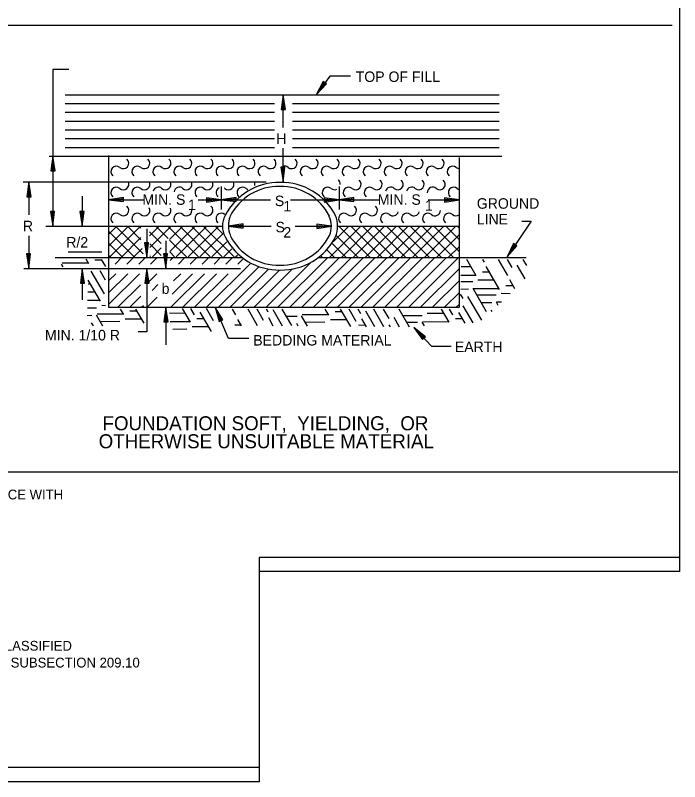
# Model space of a CAD drawing. Extents: x 0 to 390, y 0 to 265.
# Drawn here: x 271.5 to 390, y 0 to 136.7 of the extents above; entities that cross this region are included whole.
import ezdxf

# ---------------------------------------------------------------- set-up
doc = ezdxf.new("R2010")
doc.units = 0
doc.layers.add('D_Details', color=7, linetype='Continuous')
doc.layers.add('Default', color=7, linetype='Continuous')

msp = doc.modelspace()

# ---------------------------------------------------------------- linework, layer by layer
at = {"layer": 'D_Details'}
for p, q in [((-0.22, 135.01), (388.66, 135.01)), ((281.04, 127.06), (278.19, 127.06)), ((278.19, 127.06), (278.19, 111.61)), ((327.59, 125.86), (325.18, 122.57)), ((331.32, 125.86), (327.59, 125.86)), ((326.4, 124.93), (325.18, 122.57)), ((325.18, 122.57), (327.01, 124.49)), ((325.57, 123.1), (326.55, 124.82)), ((326.86, 124.6), (325.57, 123.1)), ((326.17, 123.94), (326.63, 124.76)), ((326.78, 124.65), (326.17, 123.94)), ((327.01, 124.49), (326.4, 124.93)), ((280.39, 122.57), (357.83, 122.57)), ((319.27, 122.57), (318.93, 119.95)), ((319.12, 119.95), (319.27, 121.91)), ((319.68, 119.95), (319.27, 122.57)), ((319.27, 116.71), (319.27, 122.57)), ((319.27, 121.91), (319.49, 119.95)), ((280.39, 121), (317.76, 121)), ((319.21, 119.95), (319.29, 120.88)), ((319.29, 120.88), (319.4, 119.95)), ((320.94, 121), (357.83, 121)), ((280.39, 119.44), (317.76, 119.44)), ((318.93, 119.95), (319.68, 119.95)), ((320.94, 119.44), (357.83, 119.44)), ((280.39, 117.87), (317.76, 117.87)), ((320.94, 117.87), (357.83, 117.87)), ((280.39, 116.31), (317.76, 116.31)), ((320.94, 116.31), (357.83, 116.31)), ((280.39, 114.74), (317.76, 114.74)), ((320.94, 114.74), (357.83, 114.74)), ((280.39, 113.17), (317.76, 113.17)), ((319.27, 107), (319.27, 113.06)), ((320.94, 113.17), (357.83, 113.17)), ((277.54, 111.61), (358.26, 111.61)), ((278.2, 111.61), (277.86, 108.98)), ((278.05, 108.98), (278.2, 110.95)), ((278.19, 111.61), (278.19, 107)), ((278.61, 108.98), (278.2, 111.61)), ((278.2, 110.95), (278.42, 108.98)), ((288.16, 111.72), (288.16, 84.64)), ((350.71, 84.64), (350.71, 111.39)), ((278.14, 108.98), (278.21, 109.92)), ((278.21, 109.92), (278.33, 108.98)), ((319.61, 109.63), (318.86, 109.63)), ((318.86, 109.63), (319.27, 107)), ((319.27, 107.66), (319.04, 109.63)), ((319.25, 108.69), (319.14, 109.63)), ((319.33, 109.63), (319.25, 108.69)), ((319.27, 107), (319.61, 109.63)), ((319.42, 109.63), (319.27, 107.66)), ((277.86, 108.98), (278.61, 108.98)), ((272.94, 107), (316.27, 107)), ((273.92, 107), (273.59, 104.38)), ((274.34, 104.38), (273.92, 107)), ((273.92, 107), (273.92, 101.17)), ((278.19, 107), (278.19, 99.11)), ((273.77, 104.38), (273.92, 106.35)), ((273.87, 104.38), (273.94, 105.32)), ((273.92, 106.35), (274.15, 104.38)), ((273.94, 105.32), (274.05, 104.38)), ((308.25, 106.2), (308.25, 102.07)), ((329.25, 106.2), (329.25, 102.07)), ((273.59, 104.38), (274.34, 104.38)), ((283.45, 104.48), (283.45, 99.11)), ((290.79, 104.24), (288.16, 103.83)), ((288.82, 103.83), (290.79, 104.05)), ((289.85, 103.84), (290.79, 103.96)), ((290.79, 103.49), (290.79, 104.24)), ((308.25, 103.83), (305.63, 104.16)), ((305.63, 104.16), (305.63, 103.41)), ((305.63, 103.98), (307.6, 103.83)), ((310.88, 104.24), (308.25, 103.83)), ((308.91, 103.83), (310.88, 104.05)), ((309.94, 103.84), (310.88, 103.96)), ((310.88, 103.49), (310.88, 104.24)), ((329.25, 103.83), (326.62, 104.16)), ((326.62, 104.16), (326.62, 103.41)), ((326.62, 103.98), (328.59, 103.83)), ((331.87, 104.24), (329.25, 103.83)), ((329.9, 103.83), (331.87, 104.05)), ((330.93, 103.84), (331.87, 103.96)), ((331.87, 103.49), (331.87, 104.24)), ((350.71, 103.83), (348.08, 104.16)), ((348.08, 104.16), (348.08, 103.41)), ((348.08, 103.98), (350.05, 103.83)), ((288.16, 103.83), (290.79, 103.49)), ((288.16, 103.83), (294.47, 103.83)), ((290.79, 103.68), (288.82, 103.83)), ((290.79, 103.77), (289.85, 103.84)), ((304.13, 103.83), (308.25, 103.83)), ((305.63, 103.88), (306.57, 103.81)), ((305.63, 103.41), (308.25, 103.83)), ((307.6, 103.83), (305.63, 103.6)), ((306.57, 103.81), (305.63, 103.69)), ((308.13, 103.83), (309.55, 103.83)), ((308.25, 103.83), (310.88, 103.49)), ((308.25, 103.83), (317.06, 103.83)), ((310.88, 103.68), (308.91, 103.83)), ((310.88, 103.77), (309.94, 103.84)), ((320.58, 103.83), (329.25, 103.83)), ((326.62, 103.88), (327.56, 103.81)), ((326.62, 103.41), (329.25, 103.83)), ((328.59, 103.83), (326.62, 103.6)), ((327.56, 103.81), (326.62, 103.69)), ((328.07, 103.83), (329.6, 103.83)), ((329.25, 103.83), (331.87, 103.49)), ((329.25, 103.83), (336.46, 103.83)), ((331.87, 103.68), (329.9, 103.83)), ((331.87, 103.77), (330.93, 103.84)), ((345.17, 103.83), (350.71, 103.83)), ((348.08, 103.88), (349.02, 103.81)), ((348.08, 103.41), (350.71, 103.83)), ((350.05, 103.83), (348.08, 103.6)), ((349.02, 103.81), (348.08, 103.69)), ((278.53, 101.74), (277.78, 101.74)), ((277.78, 101.74), (278.2, 99.11)), ((278.2, 99.77), (277.97, 101.74)), ((278.18, 100.8), (278.06, 101.74)), ((278.25, 101.74), (278.18, 100.8)), ((278.2, 99.11), (278.53, 101.74)), ((278.35, 101.74), (278.2, 99.77)), ((283.79, 101.74), (283.04, 101.74)), ((283.04, 101.74), (283.45, 99.11)), ((283.45, 99.77), (283.23, 101.74)), ((283.43, 100.8), (283.32, 101.74)), ((283.51, 101.74), (283.43, 100.8)), ((283.45, 99.11), (283.79, 101.74)), ((283.6, 101.74), (283.45, 99.77)), ((363.52, 99.99), (359.25, 93.63)), ((361.88, 99.99), (363.52, 99.99)), ((276.99, 99.11), (283.13, 99.11)), ((283.13, 99.11), (308.47, 99.11)), ((288.22, 97.72), (289.49, 99)), ((288.22, 95.6), (291.59, 98.97)), ((288.34, 93.6), (293.69, 98.95)), ((294.31, 94.17), (289.48, 99)), ((293.93, 96.67), (291.63, 98.97)), ((293.93, 98.79), (293.77, 98.95)), ((294.95, 98.67), (294.95, 93.52)), ((295.48, 97.4), (297.12, 99.04)), ((295.49, 95.29), (299.24, 99.04)), ((298.77, 96.92), (296.65, 99.04)), ((304.18, 93.63), (298.78, 99.04)), ((299.04, 96.72), (301.35, 99.03)), ((299.06, 94.62), (303.47, 99.02)), ((300.2, 93.63), (305.58, 99.02)), ((306.3, 93.63), (300.9, 99.03)), ((302.32, 93.63), (307.7, 99.01)), ((308.42, 93.63), (303.03, 99.03)), ((310.54, 93.63), (305.15, 99.02)), ((308.53, 97.77), (307.28, 99.02)), ((312.16, 99.52), (309.54, 99.11)), ((309.54, 99.11), (312.16, 98.77)), ((309.54, 99.11), (317.17, 99.11)), ((310.19, 99.11), (312.16, 99.34)), ((312.16, 98.96), (310.19, 99.11)), ((311.22, 99.13), (312.16, 99.24)), ((312.16, 99.06), (311.22, 99.13)), ((312.16, 98.77), (312.16, 99.52)), ((321.41, 99.11), (327.89, 99.11)), ((327.89, 99.11), (325.27, 99.45)), ((325.27, 99.45), (325.27, 98.7)), ((325.27, 99.26), (327.23, 99.11)), ((325.27, 99.17), (326.2, 99.09)), ((325.27, 98.7), (327.89, 99.11)), ((327.23, 99.11), (325.27, 98.89)), ((326.2, 99.09), (325.27, 98.98)), ((327.61, 93.59), (333.07, 99.04)), ((328.22, 96.32), (330.95, 99.04)), ((329, 99.11), (350.71, 99.11)), ((334.73, 93.58), (329.27, 99.04)), ((329.73, 93.59), (335.19, 99.04)), ((336.86, 93.58), (331.39, 99.04)), ((331.85, 93.58), (337.31, 99.04)), ((338.98, 93.57), (333.51, 99.04)), ((333.97, 93.58), (339.43, 99.04)), ((341.1, 93.57), (335.63, 99.04)), ((336.09, 93.58), (341.55, 99.04)), ((343.23, 93.57), (337.76, 99.04)), ((338.2, 93.58), (343.67, 99.04)), ((345.35, 93.57), (339.88, 99.04)), ((340.32, 93.57), (345.79, 99.04)), ((347.47, 93.56), (342, 99.04)), ((342.44, 93.57), (347.91, 99.04)), ((349.6, 93.56), (344.12, 99.04)), ((344.56, 93.57), (350.03, 99.04)), ((350.64, 94.64), (346.24, 99.04)), ((350.66, 96.74), (348.36, 99.04)), ((350.69, 98.84), (350.48, 99.04)), ((273.92, 97.41), (273.92, 91.55)), ((292.76, 93.6), (288.22, 98.14)), ((297.56, 96.01), (295.47, 98.1)), ((304.44, 93.63), (308.53, 97.73)), ((332.61, 93.58), (328.79, 97.4)), ((346.68, 93.57), (350.67, 97.56)), ((290.64, 93.6), (288.22, 96.02)), ((290.46, 93.6), (293.93, 97.07)), ((295.29, 96.15), (294.54, 96.15)), ((294.54, 96.15), (294.95, 93.52)), ((294.95, 94.18), (294.73, 96.15)), ((294.93, 95.21), (294.82, 96.15)), ((295.01, 96.15), (294.93, 95.21)), ((294.95, 93.52), (295.29, 96.15)), ((295.1, 96.15), (294.95, 94.18)), ((297.53, 93.91), (295.49, 95.96)), ((298.35, 96.48), (298.35, 91.55)), ((302.06, 93.63), (299.04, 96.65)), ((306.56, 93.63), (309.26, 96.34)), ((330.49, 93.59), (328.04, 96.03)), ((360.37, 96.04), (359.25, 93.63)), ((359.62, 94.18), (360.53, 95.94)), ((360.84, 95.73), (359.62, 94.18)), ((360.17, 95.04), (360.6, 95.88)), ((360.76, 95.78), (360.17, 95.04)), ((360.99, 95.62), (360.37, 96.04)), ((280.93, 94.51), (286.96, 94.51)), ((292.58, 93.6), (294.13, 95.15)), ((296, 93.67), (297.55, 95.23)), ((299.94, 93.63), (299.06, 94.51)), ((308.68, 93.63), (310.14, 95.1)), ((328.36, 93.59), (327.14, 94.81)), ((348.8, 93.56), (350.65, 95.41)), ((359.25, 93.63), (360.99, 95.62)), ((274.26, 94.17), (273.51, 94.17)), ((273.51, 94.17), (273.92, 91.55)), ((273.92, 92.2), (273.7, 94.17)), ((273.9, 93.24), (273.79, 94.17)), ((273.98, 94.17), (273.9, 93.24)), ((273.92, 91.55), (274.26, 94.17)), ((274.07, 94.17), (273.92, 92.2)), ((278.63, 93.52), (311.99, 93.52)), ((284.62, 92.42), (284.14, 93.24)), ((287.02, 93.03), (285.73, 93.04)), ((287.65, 91.95), (286.92, 93.2)), ((288.16, 93.34), (288.34, 93.52)), ((288.52, 93.6), (288.22, 93.9)), ((289.3, 92.35), (290.47, 93.52)), ((291.42, 92.35), (292.59, 93.52)), ((293.54, 92.35), (294.71, 93.52)), ((295.64, 93.69), (295.5, 93.83)), ((295.66, 92.35), (296.83, 93.52)), ((298.69, 94.17), (297.94, 94.17)), ((297.94, 94.17), (298.35, 91.55)), ((298.35, 92.2), (298.12, 94.17)), ((298.33, 93.24), (298.22, 94.17)), ((298.41, 94.17), (298.33, 93.24)), ((298.35, 91.55), (298.69, 94.17)), ((298.5, 94.17), (298.35, 92.2)), ((299.15, 93.02), (299.66, 93.52)), ((300.61, 92.35), (301.78, 93.52)), ((302.73, 92.35), (303.9, 93.52)), ((304.85, 92.35), (306.02, 93.52)), ((306.97, 92.35), (308.14, 93.52)), ((309.09, 92.35), (310.26, 93.52)), ((310.8, 93.63), (311.13, 93.96)), ((311.21, 92.35), (312.22, 93.36)), ((318.35, 84.64), (327.23, 93.52)), ((320.47, 84.64), (329.35, 93.52)), ((322.59, 84.64), (331.47, 93.52)), ((324.71, 84.64), (333.59, 93.52)), ((325.56, 93.52), (362.64, 93.52)), ((326.24, 93.59), (326.04, 93.79)), ((326.83, 84.64), (335.71, 93.52)), ((328.95, 84.64), (337.83, 93.52)), ((331.07, 84.64), (339.95, 93.52)), ((333.19, 84.64), (342.07, 93.52)), ((335.31, 84.64), (344.19, 93.52)), ((337.43, 84.64), (346.31, 93.52)), ((339.55, 84.64), (348.43, 93.52)), ((341.68, 84.64), (350.55, 93.52)), ((353.71, 90.25), (352.02, 93.19)), ((355.18, 92.71), (354.9, 93.19)), ((359.34, 90.3), (357.68, 93.19)), ((360.13, 91.75), (359.32, 93.19)), ((362.72, 92.11), (362.11, 93.19)), ((280.04, 91.84), (279.76, 92.33)), ((284.54, 92.51), (279.87, 92.52)), ((305.62, 84.64), (313.52, 92.54)), ((307.74, 84.64), (315.01, 91.91)), ((316.23, 84.64), (324.27, 92.69)), ((352.7, 91.87), (351.01, 91.88)), ((357.88, 87.84), (355.52, 91.93)), ((362.46, 89.72), (361.05, 92.18)), ((273.05, 91.55), (311.71, 91.55)), ((283.45, 91.55), (283.12, 88.92)), ((283.3, 88.92), (283.45, 90.89)), ((283.45, 91.55), (283.45, 85.96)), ((283.87, 88.92), (283.45, 91.55)), ((283.45, 90.89), (283.68, 88.92)), ((287.41, 87.07), (285.07, 91.11)), ((287.62, 89.49), (286.64, 91.17)), ((288.16, 91.48), (288.23, 91.55)), ((288.16, 89.36), (289.45, 90.64)), ((288.16, 87.24), (291.57, 90.64)), ((288.16, 85.12), (293.69, 90.64)), ((294.95, 91.55), (294.62, 88.92)), ((294.8, 88.92), (294.95, 90.89)), ((294.95, 91.55), (294.95, 80.26)), ((295.37, 88.92), (294.95, 91.55)), ((294.95, 90.89), (295.18, 88.92)), ((295.32, 89.19), (296.78, 90.64)), ((299.26, 84.64), (305.26, 90.64)), ((299.47, 86.98), (303.14, 90.64)), ((299.71, 89.34), (301.02, 90.64)), ((301.38, 84.64), (307.38, 90.64)), ((303.5, 84.64), (309.5, 90.64)), ((309.86, 84.64), (316.68, 91.46)), ((311.98, 84.64), (318.64, 91.29)), ((314.1, 84.64), (320.95, 91.49)), ((343.8, 84.64), (350.71, 91.55)), ((353.67, 90.32), (350.99, 90.34)), ((356.13, 90.89), (354.84, 90.9)), ((283.12, 88.92), (283.87, 88.92)), ((283.4, 88.92), (283.47, 89.86)), ((283.47, 89.86), (283.58, 88.92)), ((286.69, 85.75), (284.5, 89.47)), ((294.62, 88.92), (295.37, 88.92)), ((294.9, 88.92), (294.97, 89.86)), ((294.95, 88.82), (295.06, 88.92)), ((294.97, 89.86), (295.08, 88.92)), ((345.92, 84.64), (350.71, 89.43)), ((353.11, 89.21), (350.97, 89.2)), ((356.87, 89.47), (353.98, 89.49)), ((360.62, 87.91), (359.69, 89.53)), ((284.92, 88.76), (284.49, 88.76)), ((289.81, 84.64), (293.84, 88.67)), ((295.9, 87.65), (296.94, 88.69)), ((352.33, 87.85), (350.95, 87.84)), ((355.55, 83.82), (353.15, 87.98)), ((357.83, 87.91), (353.18, 87.96)), ((360.3, 88.48), (359, 88.49)), ((285.69, 87.32), (284.45, 87.33)), ((291.93, 84.64), (293.93, 86.64)), ((295.02, 84.64), (296.59, 86.21)), ((296.59, 86.21), (296.81, 86.44)), ((348.04, 84.64), (350.71, 87.31)), ((351.39, 86.22), (350.94, 87)), ((354.69, 82.32), (352.24, 86.55)), ((357.28, 86.8), (353.85, 86.79)), ((359.77, 87.07), (358.15, 87.08)), ((286.61, 85.84), (284.41, 85.84)), ((287.62, 84.93), (286.97, 84.94)), ((294.05, 84.64), (294.36, 84.95)), ((350.16, 84.64), (350.71, 85.19)), ((353.16, 81.88), (351.39, 84.92)), ((356.49, 85.44), (354.63, 85.43)), ((357.65, 84.99), (357.32, 85.57)), ((358.22, 85.54), (357.35, 85.55)), ((286.01, 84.5), (284.38, 84.48)), ((290.78, 83.43), (286.11, 83.44)), ((288.16, 84.64), (350.71, 84.64)), ((290.86, 83.34), (290.29, 84.31)), ((293.26, 83.95), (291.96, 83.96)), ((294.52, 81.8), (293.04, 84.31)), ((298.35, 84.64), (298.01, 82.02)), ((298.2, 82.02), (298.35, 83.99)), ((298.35, 84.64), (298.35, 77.96)), ((298.76, 82.02), (298.35, 84.64)), ((298.35, 83.99), (298.57, 82.02)), ((301.78, 83.54), (299.02, 83.57)), ((302.78, 81.97), (301.33, 84.44)), ((303.5, 83.29), (302.83, 84.44)), ((306.48, 80.35), (304.48, 83.76)), ((306.89, 82.22), (305.6, 84.44)), ((309.52, 79.05), (307.14, 84.64)), ((307.14, 84.64), (307.86, 82.1)), ((308.55, 82.39), (307.14, 84.64)), ((308.03, 82.17), (307.4, 84.04)), ((307.4, 84.04), (308.38, 82.32)), ((310.84, 83.27), (310.24, 84.31)), ((314.74, 81.32), (313.02, 84.31)), ((315.8, 82.31), (314.65, 84.31)), ((316.64, 83.77), (316.33, 84.31)), ((319.17, 81.29), (317.53, 84.17)), ((320.81, 81.37), (319.1, 84.31)), ((327.43, 83.21), (326.78, 84.31)), ((329.83, 83.82), (328.54, 83.83)), ((331.37, 81.19), (329.53, 84.31)), ((332.31, 82.13), (331.05, 84.31)), ((333.17, 83.45), (332.66, 84.31)), ((335.65, 81.16), (334.03, 83.95)), ((337.27, 81.15), (335.43, 84.31)), ((338.2, 82.62), (337.21, 84.31)), ((341.84, 81.11), (339.98, 84.31)), ((347.88, 83.53), (344.98, 83.52)), ((348.9, 81.99), (347.53, 84.31)), ((349.57, 83.29), (348.97, 84.31)), ((351.77, 81.79), (350.64, 83.71)), ((356.55, 83.9), (356.41, 84.15)), ((285.19, 83.15), (284.34, 83.14)), ((287.13, 81.29), (286, 83.25)), ((290.18, 82.09), (286.73, 82.05)), ((294.03, 82.51), (291.14, 82.53)), ((298.29, 82.02), (298.37, 82.96)), ((298.37, 82.96), (298.48, 82.02)), ((302.7, 82.06), (299.14, 82.07)), ((305.18, 82.58), (303.88, 82.59)), ((308.12, 82.21), (307.82, 83.1)), ((307.82, 83.1), (308.29, 82.28)), ((307.86, 82.1), (308.55, 82.39)), ((311.84, 81.35), (311.18, 82.49)), ((317.53, 81.3), (316.71, 82.74)), ((321.76, 83.02), (319.93, 83)), ((323.65, 81.25), (322.57, 83.12)), ((327.35, 83.3), (322.68, 83.31)), ((330.6, 82.38), (327.71, 82.4)), ((334.13, 81.17), (333.29, 82.6)), ((340.05, 81.12), (339.06, 82.82)), ((344.09, 83.12), (340.66, 83.11)), ((351.3, 82.59), (350.04, 82.59)), ((285.45, 81.33), (285.13, 81.89)), ((298.01, 82.02), (298.76, 82.02)), ((302.1, 80.72), (299.64, 80.69)), ((305.95, 81.14), (303.06, 81.16)), ((311.79, 81.45), (310.67, 81.46)), ((321.98, 81.27), (321.7, 81.76)), ((326.75, 81.96), (323.3, 81.92)), ((334, 81.42), (332.7, 81.43)), ((338.43, 81.14), (338.2, 81.54)), ((343.26, 81.91), (341.41, 81.94)), ((345.78, 77.63), (342.6, 81.03)), ((342.6, 81.03), (344.15, 78.88)), ((344.69, 79.39), (342.6, 81.03)), ((344.48, 81.33), (344.1, 81.99)), ((348.82, 81.99), (344.17, 82.04)), ((294.95, 80.26), (293.42, 80.26)), ((344.28, 79.01), (343.05, 80.55)), ((343.05, 80.55), (344.56, 79.26)), ((344.35, 79.07), (343.77, 79.81)), ((343.77, 79.81), (344.49, 79.2)), ((344.15, 78.88), (344.69, 79.39)), ((313.14, 79.05), (309.52, 79.05)), ((349.28, 77.63), (345.78, 77.63)), ((-0.22, 55.26), (389.68, 55.26))]:
    msp.add_line(p, q, dxfattribs=at)
for centre, radius, start, end in [((290.8, 110.35), 0.975, 230, 50), ((294.55, 110.35), 0.975, 230, 50), ((298.3, 110.35), 0.975, 230, 50), ((302.04, 110.35), 0.975, 230, 50), ((305.79, 110.35), 0.975, 230, 50), ((309.54, 110.35), 0.975, 230, 50), ((313.29, 110.35), 0.975, 230, 50), ((317.04, 110.35), 0.975, 230, 50), ((320.79, 110.35), 0.975, 230, 50), ((324.54, 110.35), 0.975, 230, 50), ((328.29, 110.35), 0.975, 230, 50), ((332.04, 110.35), 0.975, 230, 50), ((335.79, 110.35), 0.975, 230, 50), ((339.53, 110.35), 0.975, 230, 50), ((343.28, 110.35), 0.975, 230, 50), ((347.03, 110.35), 0.975, 230, 50), ((289.54, 108.86), 0.975, 50, 230), ((293.29, 108.86), 0.975, 50, 230), ((297.04, 108.86), 0.975, 50, 230), ((300.79, 108.86), 0.975, 50, 230), ((304.54, 108.86), 0.975, 50, 230), ((308.29, 108.86), 0.975, 50, 230), ((312.04, 108.86), 0.975, 50, 230), ((315.79, 108.86), 0.975, 50, 230), ((319.54, 108.86), 0.975, 50, 105.8586), ((323.29, 108.86), 0.975, 50, 230), ((327.03, 108.86), 0.975, 50, 230), ((330.78, 108.86), 0.975, 50, 230), ((334.53, 108.86), 0.975, 50, 230), ((338.28, 108.86), 0.975, 50, 230), ((342.03, 108.86), 0.975, 50, 230), ((345.78, 108.86), 0.975, 50, 230), ((349.53, 108.86), 0.975, 50, 230), ((350.78, 110.35), 0.975, 230, 265.5063), ((290.8, 106.6), 0.975, 230, 24.3502), ((294.55, 106.6), 0.975, 230, 24.3502), ((298.3, 106.6), 0.975, 230, 24.3502), ((302.04, 106.6), 0.975, 230, 24.3502), ((305.79, 106.6), 0.975, 230, 24.3502), ((309.54, 106.6), 0.975, 230, 24.3502), ((318.59, 96.07), 10.85, 89.0105, 152.9614), ((313.29, 106.6), 0.975, 345.0771, 24.3502), ((318.96, 96.07), 10.85, 27.0239, 90.9895), ((328.48, 106.6), 0.975, 358.8379, 50), ((332.23, 106.6), 0.975, 230, 50), ((335.98, 106.6), 0.975, 230, 50), ((339.73, 106.6), 0.975, 230, 50), ((343.47, 106.6), 0.975, 230, 50), ((347.22, 106.6), 0.975, 230, 50), ((289.54, 105.11), 0.975, 50, 230), ((293.29, 105.11), 0.975, 50, 230), ((297.04, 105.11), 0.975, 50, 166.7251), ((300.79, 105.11), 0.975, 50, 171.7619), ((304.54, 105.11), 0.975, 50, 230), ((308.29, 105.11), 0.975, 116.6089, 230), ((308.29, 105.11), 0.975, 50, 55.5377), ((318.52, 96.44), 9.77, 89.0105, 152.9614), ((312.04, 105.11), 0.975, 50, 230), ((313.29, 106.6), 0.975, 230, 251.0363), ((318.86, 96.44), 9.77, 27.0239, 90.9895), ((327.23, 105.11), 0.975, 50, 230), ((328.48, 106.6), 0.975, 230, 291.7061), ((330.97, 105.11), 0.975, 50, 230), ((334.72, 105.11), 0.975, 50, 230), ((338.47, 105.11), 0.975, 50, 163.7979), ((342.22, 105.11), 0.975, 50, 163.7896), ((345.97, 105.11), 0.975, 50, 181.418), ((349.72, 105.11), 0.975, 50, 230), ((350.97, 106.6), 0.975, 230, 254.0929), ((290.8, 101.94), 0.975, 230, 50), ((305.79, 101.94), 0.975, 230, 50), ((331.38, 101.94), 0.975, 230, 50), ((335.13, 101.94), 0.975, 230, 50), ((289.54, 100.44), 0.975, 50, 230), ((293.29, 100.44), 0.975, 50, 230), ((294.55, 101.94), 0.975, 230, 27.8977), ((297.04, 100.44), 0.975, 50, 230), ((298.3, 101.94), 0.975, 230, 25.1429), ((300.79, 100.44), 0.975, 50, 230), ((302.04, 101.94), 0.975, 230, 16.1995), ((304.54, 100.44), 0.975, 50, 230), ((308.29, 100.44), 0.975, 50, 230), ((330.13, 100.44), 0.975, 50, 230), ((333.88, 100.44), 0.975, 50, 230), ((337.62, 100.44), 0.975, 50, 230), ((338.88, 101.94), 0.975, 230, 343.5766), ((341.37, 100.44), 0.975, 50, 230), ((342.63, 101.94), 0.975, 230, 342.9577), ((345.12, 100.44), 0.975, 50, 230), ((346.38, 101.94), 0.975, 230, 358.7689), ((348.87, 100.44), 0.975, 50, 230), ((350.12, 101.94), 0.975, 230, 306.5651), ((312.64, 99.12), 4.17, 153.1162, 207.2156), ((314.15, 99.27), 4.62, 159.705, 202.7349), ((323.79, 99.07), 4.1, 336.8428, 25.5612), ((324.09, 99.07), 4.91, 337.7119, 23.0815), ((318.59, 102.14), 10.85, 207.0386, 270.9895), ((318.52, 101.9), 9.77, 207.0386, 270.9895), ((318.86, 101.9), 9.77, 269.0105, 332.9761), ((318.96, 102.14), 10.85, 269.0105, 332.9761)]:
    msp.add_arc(centre, radius, start, end, dxfattribs=at)
at = {"layer": 'Default'}
for points in [[(0, 265), (326.25, 265), (326.25, 255), (390, 255), (390, 37.5), (315, 37.5), (315, 0), (0, 0)], [(0, 262.5), (326.25, 262.5), (326.25, 252.5), (390, 252.5), (390, 40), (315, 40), (315, 2.5), (0, 2.5)]]:
    msp.add_lwpolyline(points, close=True, dxfattribs=at)

# ---------------------------------------------------------------- texts
at = {"layer": 'D_Details'}
for s, height, p in [('TOP OF FILL', 1.8745, (332.23, 124.85)), ('H', 1.87, (318.07, 113.79)), ('MIN. S', 1.875, (294.19, 102.93)), ('S', 1.87, (317.81, 102.7)), ('MIN. S', 1.875, (336.17, 102.93)), ('GROUND', 1.875, (353.82, 102.23)), ('1', 1.87, (302.33, 101.99)), ('1', 1.87, (319.33, 101.76)), ('1', 1.87, (344.58, 101.88)), ('LINE', 1.875, (353.82, 99.42)), ('R', 1.87, (272.87, 98.22)), ('S', 1.87, (317.93, 98.02)), ('2', 1.87, (319.33, 97.09)), ('R/2', 1.875, (280.61, 95.31)), ('b', 1.87, (297.62, 87.04)), ('MIN. 1/10 R', 1.8745, (276.81, 78.73)), ('BEDDING MATERIAL', 1.8745, (313.96, 77.82)), ('EARTH', 1.875, (349.91, 76.65)), ('FOUNDATION SOFT,  YIELDING,  OR', 2.4994, (287.07, 62.7)), ('OTHERWISE UNSUITABLE MATERIAL', 2.4994, (286.38, 59.49)), ('FOUNDATION FILL MATERIAL IN ACCORDANCE WITH', 1.7496, (220, 50.36)), ('SUITABLE ROADWAY EXCAVATION OR UNCLASSIFIED', 1.7496, (220, 23.37)), ('BORROW MATERIAL IN ACCORDANCE WITH SUBSECTION 209.10', 1.7496, (220, 20.37))]:
    msp.add_text(s, height=height, dxfattribs=at).set_placement(p)

doc.saveas('drawing.dxf')
